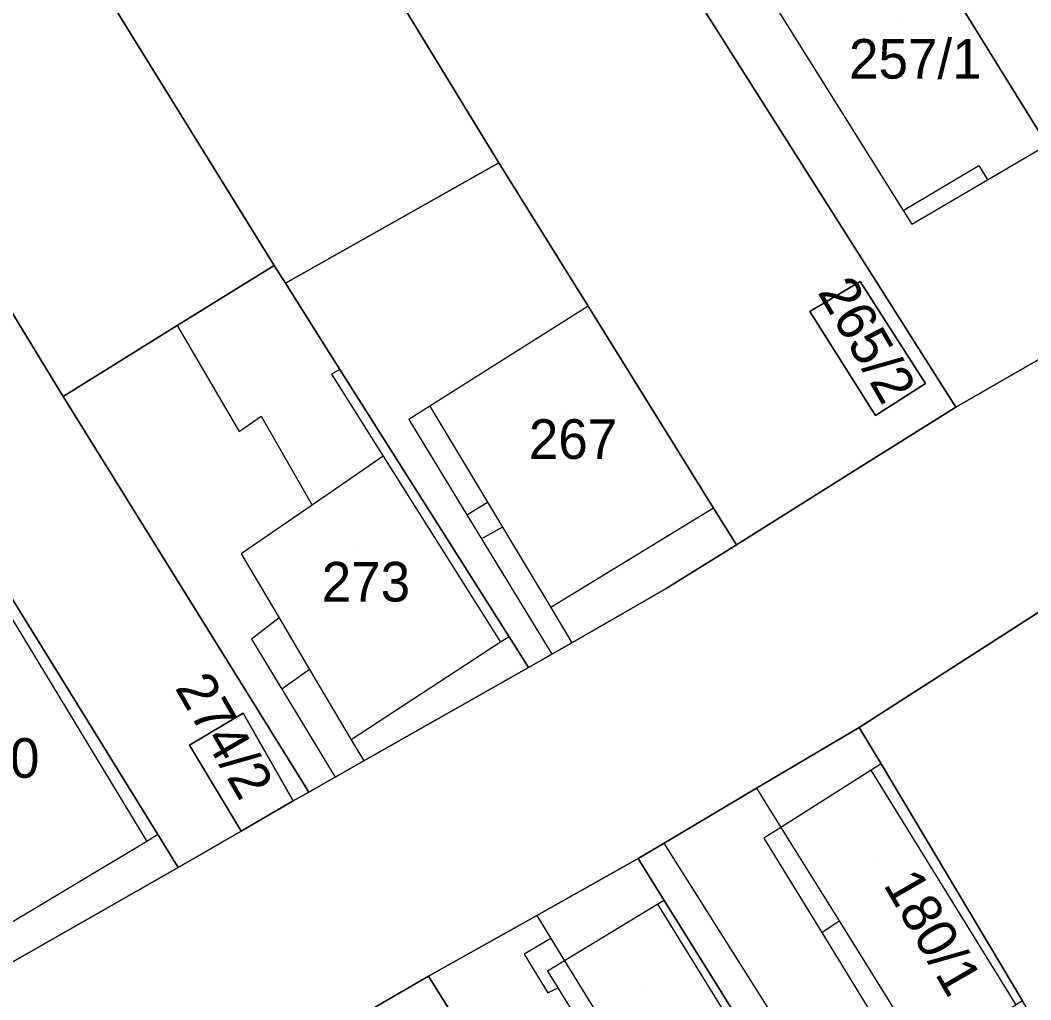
# Model space of a CAD drawing. Extents: x -263943 to -261149, y -1236934 to -1230686.
# Drawn here: x -262473.7 to -262422.7, y -1235693.4 to -1235644 of the extents above; entities that cross this region are included whole.
import ezdxf

# ---------------------------------------------------------------- set-up
doc = ezdxf.new("R2010")
doc.units = 0
for name, color, linetype in [('body_kn', 7, 'Continuous'), ('kladpar_druhypozemkov', 7, 'Continuous'), ('kladpar_hranice', 7, 'Continuous'), ('kladpar_parcelnecisla', 7, 'Continuous'), ('kladpar_plochy', 7, 'Continuous'), ('zappar_hrandruhpozemk', 7, 'Continuous')]:
    doc.layers.add(name, color=color, linetype=linetype)

msp = doc.modelspace()

# ---------------------------------------------------------------- linework, layer by layer
at = {"layer": 'body_kn'}
for p, q in [((-262449.55, -1235651.19), (-262449.55, -1235651.19)), ((-262425.32, -1235651.33), (-262425.32, -1235651.33)), ((-262424.88, -1235652.05), (-262424.88, -1235652.05)), ((-262429.14, -1235653.59), (-262429.14, -1235653.59)), ((-262428.7, -1235654.29), (-262428.7, -1235654.29)), ((-262460.89, -1235656.37), (-262460.89, -1235656.37)), ((-262460.32, -1235657.27), (-262460.32, -1235657.27)), ((-262431.32, -1235657.18), (-262431.32, -1235657.18)), ((-262445.05, -1235658.43), (-262445.05, -1235658.43)), ((-262445.05, -1235658.43), (-262445.05, -1235658.43)), ((-262433.86, -1235658.7), (-262433.86, -1235658.7)), ((-262433.86, -1235658.7), (-262433.86, -1235658.7)), ((-262465.79, -1235659.41), (-262465.79, -1235659.41)), ((-262465.79, -1235659.41), (-262465.79, -1235659.41)), ((-262457.57, -1235661.62), (-262457.57, -1235661.62)), ((-262457.57, -1235661.62), (-262457.57, -1235661.62)), ((-262458, -1235661.87), (-262458, -1235661.87)), ((-262428.01, -1235662.34), (-262428.01, -1235662.34)), ((-262471.55, -1235662.99), (-262471.55, -1235662.99)), ((-262453.03, -1235663.48), (-262453.03, -1235663.48)), ((-262426.48, -1235663.52), (-262426.48, -1235663.52)), ((-262461.55, -1235663.99), (-262461.55, -1235663.99)), ((-262454.09, -1235664.15), (-262454.09, -1235664.15)), ((-262430.54, -1235663.95), (-262430.54, -1235663.95)), ((-262462.65, -1235664.76), (-262462.65, -1235664.76)), ((-262455.39, -1235666.01), (-262455.39, -1235666.01)), ((-262431.89, -1235666.91), (-262431.89, -1235666.91)), ((-262458.97, -1235668.48), (-262458.97, -1235668.48)), ((-262450.12, -1235668.33), (-262450.12, -1235668.33)), ((-262438.72, -1235668.62), (-262438.72, -1235668.62)), ((-262438.72, -1235668.62), (-262438.72, -1235668.62)), ((-262451.16, -1235668.96), (-262451.16, -1235668.96)), ((-262451.16, -1235668.96), (-262451.16, -1235668.96)), ((-262449.36, -1235669.59), (-262449.36, -1235669.59)), ((-262449.36, -1235669.59), (-262449.36, -1235669.59)), ((-262450.42, -1235670.18), (-262450.42, -1235670.18)), ((-262437.56, -1235670.48), (-262437.56, -1235670.48)), ((-262437.56, -1235670.48), (-262437.56, -1235670.48)), ((-262462.55, -1235670.94), (-262462.55, -1235670.94)), ((-262441.11, -1235672.69), (-262441.11, -1235672.69)), ((-262441.11, -1235672.69), (-262441.11, -1235672.69)), ((-262446.93, -1235673.64), (-262446.93, -1235673.64)), ((-262446.93, -1235673.64), (-262446.93, -1235673.64)), ((-262460.64, -1235674.17), (-262460.64, -1235674.17)), ((-262462.03, -1235675.25), (-262462.03, -1235675.25)), ((-262449.47, -1235675.4), (-262449.47, -1235675.4)), ((-262449.47, -1235675.4), (-262449.47, -1235675.4)), ((-262449.03, -1235675.12), (-262449.03, -1235675.12)), ((-262449.03, -1235675.12), (-262449.03, -1235675.12)), ((-262445.86, -1235675.42), (-262445.86, -1235675.42)), ((-262446.88, -1235676), (-262446.88, -1235676)), ((-262459.1, -1235676.77), (-262459.1, -1235676.77)), ((-262459.1, -1235676.77), (-262459.1, -1235676.77)), ((-262448.05, -1235676.67), (-262448.05, -1235676.67)), ((-262448.02, -1235676.65), (-262448.02, -1235676.65)), ((-262460.51, -1235677.77), (-262460.51, -1235677.77)), ((-262462.45, -1235678.98), (-262462.45, -1235678.98)), ((-262462.45, -1235678.98), (-262462.45, -1235678.98)), ((-262431.36, -1235679.7), (-262431.36, -1235679.7)), ((-262457, -1235680.32), (-262457, -1235680.32)), ((-262457, -1235680.32), (-262457, -1235680.32)), ((-262465.16, -1235680.59), (-262465.16, -1235680.59)), ((-262465.16, -1235680.59), (-262465.16, -1235680.59)), ((-262456.37, -1235681.39), (-262456.37, -1235681.39)), ((-262430.26, -1235681.54), (-262430.26, -1235681.54)), ((-262430.26, -1235681.54), (-262430.26, -1235681.54)), ((-262430.76, -1235681.86), (-262430.76, -1235681.86)), ((-262430.76, -1235681.86), (-262430.76, -1235681.86)), ((-262457.82, -1235682.21), (-262457.82, -1235682.21)), ((-262457.82, -1235682.21), (-262457.82, -1235682.21)), ((-262459.14, -1235682.96), (-262459.14, -1235682.96)), ((-262436.54, -1235682.77), (-262436.54, -1235682.77)), ((-262436.54, -1235682.77), (-262436.54, -1235682.77)), ((-262459.93, -1235683.41), (-262459.93, -1235683.41)), ((-262466.76, -1235685.11), (-262466.76, -1235685.11)), ((-262466.76, -1235685.11), (-262466.76, -1235685.11)), ((-262462.55, -1235684.93), (-262462.55, -1235684.93)), ((-262435.31, -1235684.75), (-262435.31, -1235684.75)), ((-262467.32, -1235685.45), (-262467.32, -1235685.45)), ((-262467.32, -1235685.45), (-262467.32, -1235685.45)), ((-262441.21, -1235685.54), (-262441.21, -1235685.54)), ((-262436.17, -1235685.29), (-262436.17, -1235685.29)), ((-262442.52, -1235686.32), (-262442.52, -1235686.32)), ((-262465.73, -1235686.77), (-262465.73, -1235686.77)), ((-262441.53, -1235688.62), (-262441.53, -1235688.62)), ((-262441.21, -1235688.43), (-262441.21, -1235688.43)), ((-262441.21, -1235688.43), (-262441.21, -1235688.43)), ((-262447.64, -1235689.19), (-262447.64, -1235689.19)), ((-262447.64, -1235689.19), (-262447.64, -1235689.19)), ((-262432.37, -1235689.47), (-262432.37, -1235689.47)), ((-262432.37, -1235689.47), (-262432.37, -1235689.47)), ((-262433.24, -1235690.06), (-262433.24, -1235690.06)), ((-262446.92, -1235690.35), (-262446.92, -1235690.35)), ((-262448.27, -1235691.15), (-262448.27, -1235691.15)), ((-262446.23, -1235691.48), (-262446.23, -1235691.48)), ((-262447.09, -1235692), (-262447.09, -1235692)), ((-262453.1, -1235692.26), (-262453.1, -1235692.26)), ((-262447.08, -1235693.1), (-262447.08, -1235693.1)), ((-262446.57, -1235692.84), (-262446.57, -1235692.84))]:
    msp.add_line(p, q, dxfattribs=at)
at = {"layer": 'kladpar_druhypozemkov'}
for p, q in [((-262429.1, -1235644.09), (-262429.1, -1235644.09)), ((-262429.65, -1235660.84), (-262429.65, -1235660.84)), ((-262446.15, -1235663.59), (-262446.15, -1235663.59)), ((-262456.75, -1235670.59), (-262456.75, -1235670.59)), ((-262461.3, -1235682.49), (-262461.3, -1235682.49)), ((-262430.62, -1235686.45), (-262430.62, -1235686.45)), ((-262442.07, -1235692.7), (-262442.07, -1235692.7))]:
    msp.add_line(p, q, dxfattribs=at)
at = {"layer": 'kladpar_hranice'}
msp.add_line((-262431.89, -1235666.91), (-262437.56, -1235670.48), dxfattribs=at)
for points in [[(-262437.56, -1235670.48), (-262438.72, -1235668.62), (-262445.05, -1235658.43), (-262449.55, -1235651.19), (-262470.31, -1235617.16), (-262473.1, -1235612.61), (-262462.61, -1235605.99), (-262459.97, -1235610.31), (-262445.18, -1235634), (-262426.48, -1235663.52), (-262431.89, -1235666.91)], [(-262462.45, -1235678.98), (-262465.16, -1235680.59), (-262462.55, -1235684.93), (-262465.73, -1235686.77), (-262466.76, -1235685.11), (-262476.87, -1235668.76), (-262501.1, -1235628.68), (-262502.89, -1235625.71), (-262504.3, -1235623.37), (-262502.52, -1235622.26), (-262494.26, -1235617.1), (-262493.84, -1235616.84), (-262490.7, -1235621.87), (-262494.68, -1235625.01), (-262471.55, -1235662.99), (-262459.14, -1235682.96), (-262459.93, -1235683.41), (-262462.45, -1235678.98)], [(-262481.06, -1235623.8), (-262470.31, -1235617.16), (-262449.55, -1235651.19), (-262460.32, -1235657.27), (-262460.89, -1235656.37), (-262481.06, -1235623.8)], [(-262494.68, -1235625.01), (-262490.7, -1235621.87), (-262484.52, -1235618.05), (-262481.06, -1235623.8), (-262460.89, -1235656.37), (-262465.79, -1235659.41), (-262471.55, -1235662.99), (-262494.68, -1235625.01)], [(-262405.02, -1235652.52), (-262405.24, -1235652.65), (-262406.68, -1235652.15), (-262414.15, -1235656.44), (-262417.03, -1235658.09), (-262421.87, -1235650.28), (-262427.39, -1235641.37), (-262424.41, -1235639.64), (-262427.56, -1235634.48), (-262430.56, -1235636.27), (-262432.72, -1235632.78), (-262424.94, -1235628.36), (-262421.69, -1235626.51), (-262421.39, -1235626.34), (-262406.69, -1235649.85), (-262405.02, -1235652.52)], [(-262421.87, -1235650.28), (-262417.03, -1235658.09), (-262426.48, -1235663.52), (-262445.18, -1235634), (-262435.54, -1235628.23), (-262432.72, -1235632.78), (-262430.56, -1235636.27), (-262428.71, -1235639.25), (-262427.39, -1235641.37), (-262421.87, -1235650.28)], [(-262474.36, -1235691.68), (-262465.73, -1235686.77), (-262462.55, -1235684.93), (-262459.93, -1235683.41), (-262459.14, -1235682.96), (-262457.82, -1235682.21), (-262456.37, -1235681.39), (-262448.05, -1235676.67), (-262448.02, -1235676.65), (-262446.88, -1235676), (-262445.86, -1235675.42), (-262441.11, -1235672.69), (-262437.56, -1235670.48), (-262431.89, -1235666.91), (-262426.48, -1235663.52), (-262417.03, -1235658.09), (-262414.15, -1235656.44), (-262406.68, -1235652.15), (-262405.24, -1235652.65), (-262405.02, -1235652.52), (-262390.77, -1235644)], [(-262441.11, -1235672.69), (-262445.86, -1235675.42), (-262446.88, -1235676), (-262448.02, -1235676.65), (-262448.05, -1235676.67), (-262449.03, -1235675.12), (-262457.57, -1235661.62), (-262460.32, -1235657.27), (-262449.55, -1235651.19), (-262445.05, -1235658.43), (-262438.72, -1235668.62), (-262437.56, -1235670.48), (-262441.11, -1235672.69)], [(-262386.09, -1235651.95), (-262400.14, -1235660.44), (-262411.31, -1235667.14), (-262420.78, -1235672.91), (-262431.36, -1235679.7), (-262436.54, -1235682.77), (-262441.21, -1235685.54), (-262442.52, -1235686.32), (-262447.64, -1235689.19), (-262453.1, -1235692.26), (-262459.88, -1235696.19), (-262465.59, -1235699.5), (-262468.92, -1235701.43), (-262480.77, -1235708.26)], [(-262457.82, -1235682.21), (-262459.14, -1235682.96), (-262471.55, -1235662.99), (-262465.79, -1235659.41), (-262460.89, -1235656.37), (-262460.32, -1235657.27), (-262457.57, -1235661.62), (-262449.03, -1235675.12), (-262448.05, -1235676.67), (-262456.37, -1235681.39), (-262457.82, -1235682.21)], [(-262431.32, -1235657.18), (-262433.86, -1235658.7), (-262430.54, -1235663.95), (-262428.01, -1235662.34), (-262431.32, -1235657.18)], [(-262433.86, -1235658.7), (-262431.32, -1235657.18), (-262428.01, -1235662.34), (-262430.54, -1235663.95), (-262433.86, -1235658.7)], [(-262466.76, -1235685.11), (-262465.73, -1235686.77), (-262474.36, -1235691.68), (-262475.23, -1235692.18), (-262477.07, -1235693.23), (-262477.92, -1235693.4), (-262489.57, -1235674.36), (-262482.2, -1235672.07), (-262477.28, -1235669.01), (-262476.87, -1235668.76), (-262466.76, -1235685.11)], [(-262402.62, -1235726.91), (-262418.09, -1235701.95), (-262420.69, -1235697.59), (-262423.12, -1235693.51), (-262430.26, -1235681.54), (-262431.36, -1235679.7), (-262420.78, -1235672.91), (-262420.55, -1235673.28), (-262407.94, -1235693.89), (-262386.6, -1235727.98), (-262384.56, -1235731.37), (-262394.71, -1235739.59), (-262402.62, -1235726.91)], [(-262465.16, -1235680.59), (-262462.45, -1235678.98), (-262459.93, -1235683.41), (-262462.55, -1235684.93), (-262465.16, -1235680.59)], [(-262423.44, -1235693.71), (-262427.99, -1235696.52), (-262428.93, -1235697.1), (-262432.51, -1235699.31), (-262433.89, -1235700.16), (-262441.21, -1235688.43), (-262442.52, -1235686.32), (-262441.21, -1235685.54), (-262436.54, -1235682.77), (-262431.36, -1235679.7), (-262430.26, -1235681.54), (-262423.12, -1235693.51), (-262423.44, -1235693.71)], [(-262440.6, -1235712.31), (-262444.47, -1235706.1), (-262451.96, -1235694.09), (-262453.1, -1235692.26), (-262447.64, -1235689.19), (-262442.52, -1235686.32), (-262441.21, -1235688.43), (-262433.89, -1235700.16), (-262431.57, -1235703.89), (-262430.28, -1235705.95), (-262440.6, -1235712.31)], [(-262438.35, -1235717.28), (-262436.26, -1235720.52), (-262437.54, -1235721.32), (-262436.85, -1235722.38), (-262438.04, -1235723.06), (-262438.67, -1235722.03), (-262442.29, -1235724.3), (-262445.33, -1235719.34), (-262447.04, -1235716.62), (-262451.09, -1235710.17), (-262458.62, -1235698.2), (-262459.88, -1235696.19), (-262453.1, -1235692.26), (-262451.96, -1235694.09), (-262444.47, -1235706.1), (-262440.6, -1235712.31), (-262437.77, -1235716.92), (-262438.35, -1235717.28)]]:
    msp.add_lwpolyline(points, dxfattribs=at)
at = {"layer": 'kladpar_plochy'}
for p, q in [((-262449.55, -1235651.19), (-262470.31, -1235617.16)), ((-262445.18, -1235634), (-262426.48, -1235663.52)), ((-262445.05, -1235658.43), (-262449.55, -1235651.19)), ((-262431.32, -1235657.18), (-262433.86, -1235658.7)), ((-262428.01, -1235662.34), (-262431.32, -1235657.18)), ((-262438.72, -1235668.62), (-262445.05, -1235658.43)), ((-262433.86, -1235658.7), (-262430.54, -1235663.95)), ((-262430.54, -1235663.95), (-262428.01, -1235662.34)), ((-262426.48, -1235663.52), (-262431.89, -1235666.91)), ((-262431.89, -1235666.91), (-262437.56, -1235670.48)), ((-262437.56, -1235670.48), (-262438.72, -1235668.62))]:
    msp.add_line(p, q, dxfattribs=at)
for points in [[(-262462.45, -1235678.98), (-262465.16, -1235680.59), (-262462.55, -1235684.93), (-262465.73, -1235686.77), (-262466.76, -1235685.11), (-262476.87, -1235668.76), (-262501.1, -1235628.68), (-262502.89, -1235625.71), (-262504.3, -1235623.37), (-262502.52, -1235622.26), (-262494.26, -1235617.1), (-262493.84, -1235616.84), (-262490.7, -1235621.87), (-262494.68, -1235625.01), (-262471.55, -1235662.99), (-262459.14, -1235682.96), (-262459.93, -1235683.41)], [(-262481.06, -1235623.8), (-262470.31, -1235617.16), (-262449.55, -1235651.19), (-262460.32, -1235657.27), (-262460.89, -1235656.37)], [(-262494.68, -1235625.01), (-262490.7, -1235621.87), (-262484.52, -1235618.05), (-262481.06, -1235623.8), (-262460.89, -1235656.37), (-262465.79, -1235659.41), (-262471.55, -1235662.99)], [(-262405.02, -1235652.52), (-262405.24, -1235652.65), (-262406.68, -1235652.15), (-262414.15, -1235656.44), (-262417.03, -1235658.09), (-262421.87, -1235650.28), (-262427.39, -1235641.37), (-262424.41, -1235639.64), (-262427.56, -1235634.48), (-262430.56, -1235636.27), (-262432.72, -1235632.78), (-262424.94, -1235628.36), (-262421.69, -1235626.51), (-262421.39, -1235626.34), (-262406.69, -1235649.85)], [(-262421.87, -1235650.28), (-262417.03, -1235658.09), (-262426.48, -1235663.52), (-262445.18, -1235634), (-262435.54, -1235628.23), (-262432.72, -1235632.78), (-262430.56, -1235636.27), (-262428.71, -1235639.25), (-262427.39, -1235641.37)], [(-262441.11, -1235672.69), (-262445.86, -1235675.42), (-262446.88, -1235676), (-262448.02, -1235676.65), (-262448.05, -1235676.67), (-262449.03, -1235675.12), (-262457.57, -1235661.62), (-262460.32, -1235657.27), (-262449.55, -1235651.19), (-262445.05, -1235658.43), (-262438.72, -1235668.62), (-262437.56, -1235670.48)], [(-262457.82, -1235682.21), (-262459.14, -1235682.96), (-262471.55, -1235662.99), (-262465.79, -1235659.41), (-262460.89, -1235656.37), (-262460.32, -1235657.27), (-262457.57, -1235661.62), (-262449.03, -1235675.12), (-262448.05, -1235676.67), (-262456.37, -1235681.39)], [(-262433.86, -1235658.7), (-262431.32, -1235657.18), (-262428.01, -1235662.34), (-262430.54, -1235663.95)], [(-262466.76, -1235685.11), (-262465.73, -1235686.77), (-262474.36, -1235691.68), (-262475.23, -1235692.18), (-262477.07, -1235693.23), (-262477.92, -1235693.4), (-262489.57, -1235674.36), (-262482.2, -1235672.07), (-262477.28, -1235669.01), (-262476.87, -1235668.76)], [(-262402.62, -1235726.91), (-262418.09, -1235701.95), (-262420.69, -1235697.59), (-262423.12, -1235693.51), (-262430.26, -1235681.54), (-262431.36, -1235679.7), (-262420.78, -1235672.91), (-262420.55, -1235673.28), (-262407.94, -1235693.89), (-262386.6, -1235727.98), (-262384.56, -1235731.37), (-262394.71, -1235739.59)], [(-262465.16, -1235680.59), (-262462.45, -1235678.98), (-262459.93, -1235683.41), (-262462.55, -1235684.93)], [(-262423.44, -1235693.71), (-262427.99, -1235696.52), (-262428.93, -1235697.1), (-262432.51, -1235699.31), (-262433.89, -1235700.16), (-262441.21, -1235688.43), (-262442.52, -1235686.32), (-262441.21, -1235685.54), (-262436.54, -1235682.77), (-262431.36, -1235679.7), (-262430.26, -1235681.54), (-262423.12, -1235693.51)], [(-262440.6, -1235712.31), (-262444.47, -1235706.1), (-262451.96, -1235694.09), (-262453.1, -1235692.26), (-262447.64, -1235689.19), (-262442.52, -1235686.32), (-262441.21, -1235688.43), (-262433.89, -1235700.16), (-262431.57, -1235703.89), (-262430.28, -1235705.95)], [(-262438.35, -1235717.28), (-262436.26, -1235720.52), (-262437.54, -1235721.32), (-262436.85, -1235722.38), (-262438.04, -1235723.06), (-262438.67, -1235722.03), (-262442.29, -1235724.3), (-262445.33, -1235719.34), (-262447.04, -1235716.62), (-262451.09, -1235710.17), (-262458.62, -1235698.2), (-262459.88, -1235696.19), (-262453.1, -1235692.26), (-262451.96, -1235694.09), (-262444.47, -1235706.1), (-262440.6, -1235712.31), (-262437.77, -1235716.92)]]:
    msp.add_lwpolyline(points, close=True, dxfattribs=at)
for points in [[(-262474.36, -1235691.68), (-262465.73, -1235686.77), (-262462.55, -1235684.93), (-262459.93, -1235683.41), (-262459.14, -1235682.96), (-262457.82, -1235682.21), (-262456.37, -1235681.39), (-262448.05, -1235676.67), (-262448.02, -1235676.65), (-262446.88, -1235676), (-262445.86, -1235675.42), (-262441.11, -1235672.69), (-262437.56, -1235670.48), (-262431.89, -1235666.91), (-262426.48, -1235663.52), (-262417.03, -1235658.09), (-262414.15, -1235656.44), (-262406.68, -1235652.15), (-262405.24, -1235652.65), (-262405.02, -1235652.52), (-262390.77, -1235644)], [(-262386.09, -1235651.95), (-262400.14, -1235660.44), (-262411.31, -1235667.14), (-262420.78, -1235672.91), (-262431.36, -1235679.7), (-262436.54, -1235682.77), (-262441.21, -1235685.54), (-262442.52, -1235686.32), (-262447.64, -1235689.19), (-262453.1, -1235692.26), (-262459.88, -1235696.19), (-262465.59, -1235699.5), (-262468.92, -1235701.43), (-262480.77, -1235708.26)]]:
    msp.add_lwpolyline(points, dxfattribs=at)
at = {"layer": 'zappar_hrandruhpozemk'}
for p, q in [((-262435.59, -1235643.3), (-262429.14, -1235653.59)), ((-262429.14, -1235653.59), (-262425.32, -1235651.33)), ((-262425.32, -1235651.33), (-262424.88, -1235652.05)), ((-262445.05, -1235658.43), (-262453.03, -1235663.48)), ((-262455.39, -1235666.01), (-262449.47, -1235675.4)), ((-262451.16, -1235668.96), (-262450.12, -1235668.33)), ((-262438.72, -1235668.62), (-262446.93, -1235673.64)), ((-262449.36, -1235669.59), (-262450.42, -1235670.18)), ((-262462.55, -1235670.94), (-262460.64, -1235674.17)), ((-262474.32, -1235673.89), (-262467.32, -1235685.45)), ((-262446.93, -1235673.64), (-262445.86, -1235675.42)), ((-262449.47, -1235675.4), (-262457, -1235680.32)), ((-262449.03, -1235675.12), (-262449.47, -1235675.4)), ((-262459.1, -1235676.77), (-262460.51, -1235677.77)), ((-262457, -1235680.32), (-262456.37, -1235681.39)), ((-262430.26, -1235681.54), (-262430.76, -1235681.86)), ((-262430.76, -1235681.86), (-262435.31, -1235684.75)), ((-262423.44, -1235693.71), (-262430.76, -1235681.86)), ((-262436.54, -1235682.77), (-262435.31, -1235684.75)), ((-262466.76, -1235685.11), (-262467.32, -1235685.45)), ((-262435.31, -1235684.75), (-262432.37, -1235689.47)), ((-262432.51, -1235699.31), (-262441.21, -1235685.54)), ((-262447.64, -1235689.19), (-262446.92, -1235690.35)), ((-262433.24, -1235690.06), (-262432.37, -1235689.47)), ((-262432.37, -1235689.47), (-262429.11, -1235694.71)), ((-262433.24, -1235690.06), (-262430.01, -1235695.33))]:
    msp.add_line(p, q, dxfattribs=at)
for points in [[(-262429.14, -1235653.59), (-262428.7, -1235654.29), (-262424.88, -1235652.05), (-262421.87, -1235650.28)], [(-262465.79, -1235659.41), (-262462.65, -1235664.76), (-262461.55, -1235663.99), (-262458.97, -1235668.48)], [(-262457.57, -1235661.62), (-262458, -1235661.87), (-262455.39, -1235666.01)], [(-262453.03, -1235663.48), (-262454.09, -1235664.15), (-262451.16, -1235668.96), (-262450.42, -1235670.18), (-262446.88, -1235676)], [(-262453.03, -1235663.48), (-262450.12, -1235668.33), (-262449.36, -1235669.59), (-262446.93, -1235673.64)], [(-262455.39, -1235666.01), (-262458.97, -1235668.48), (-262462.55, -1235670.94)], [(-262460.64, -1235674.17), (-262462.03, -1235675.25), (-262460.51, -1235677.77), (-262457.82, -1235682.21)], [(-262460.64, -1235674.17), (-262459.1, -1235676.77), (-262457, -1235680.32)], [(-262467.32, -1235685.45), (-262475.22, -1235690.18), (-262482, -1235678.66)], [(-262435.31, -1235684.75), (-262436.17, -1235685.29), (-262433.24, -1235690.06)], [(-262441.21, -1235688.43), (-262441.53, -1235688.62), (-262446.23, -1235691.48), (-262447.09, -1235692), (-262446.57, -1235692.84), (-262444.71, -1235695.88)], [(-262431.94, -1235704.12), (-262434, -1235700.79), (-262441.53, -1235688.62)], [(-262446.92, -1235690.35), (-262448.27, -1235691.15), (-262447.08, -1235693.1), (-262446.57, -1235692.84)], [(-262446.92, -1235690.35), (-262446.23, -1235691.48), (-262443.83, -1235695.38), (-262438.69, -1235703.7)]]:
    msp.add_lwpolyline(points, dxfattribs=at)

# ---------------------------------------------------------------- texts
at = {"layer": 'kladpar_parcelnecisla'}
for s, p in [('257/1', (-262431.874, -1235646.94)), ('267', (-262448.038, -1235666.14)), ('273', (-262458.491, -1235673.34)), ('280', (-262477.199, -1235682.24))]:
    msp.add_text(s, height=2, dxfattribs=at).set_placement(p)
for s, p in [('265/2', (-262433.49, -1235657.714)), ('274/2', (-262465.929, -1235677.693)), ('180/1', (-262430.168, -1235687.627))]:
    msp.add_text(s, height=2, rotation=300, dxfattribs=at).set_placement(p)

doc.saveas('drawing.dxf')
